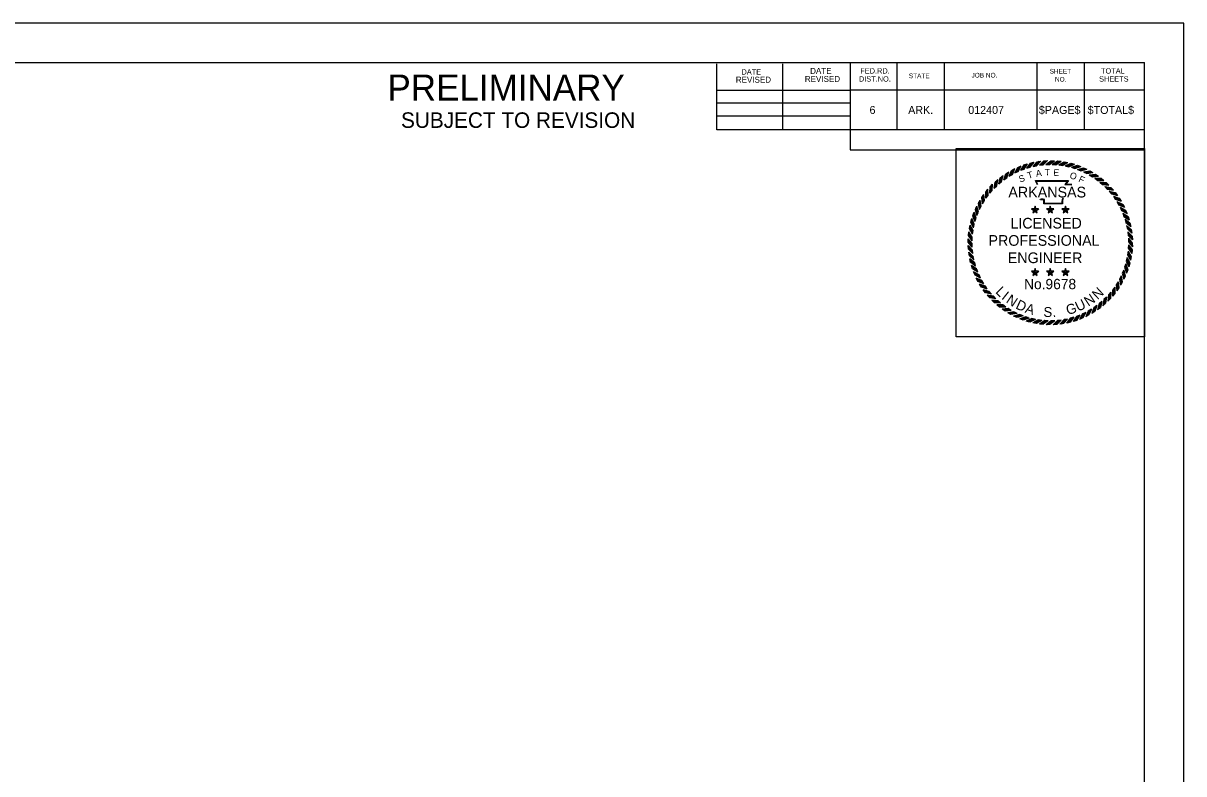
# Model space of a CAD drawing. Extents: x 0 to 1228740, y 0 to 152440.
# Drawn here: x 17 to 34, y 11 to 22 of the extents above; entities that cross this region are included whole.
import ezdxf

# ---------------------------------------------------------------- set-up
doc = ezdxf.new("R2010")
doc.units = 0
for name, color, linetype in [('R_Border', 7, 'Continuous'), ('R_Draft', 7, 'Continuous'), ('R_No Plot', 7, 'Continuous'), ('STAMP', 7, 'Continuous')]:
    doc.layers.add(name, color=color, linetype=linetype)

msp = doc.modelspace()

# ---------------------------------------------------------------- linework, layer by layer
at = {"layer": 'R_Border'}
for p, q in [((1.516, 21.423), (33.423, 21.423)), ((29.113, 21.423), (29.113, 20.143)), ((29.797, 21.423), (29.797, 20.435)), ((30.491, 21.423), (30.491, 20.435)), ((31.849, 21.423), (31.849, 20.435)), ((32.543, 21.423), (32.543, 20.435)), ((33.423, 0.577), (33.423, 21.423)), ((27.159, 20.435), (27.159, 21.403)), ((28.127, 20.435), (28.127, 21.403)), ((33.423, 21.131), (33.423, 21.131)), ((27.159, 21.021), (29.113, 21.021)), ((33.423, 21.021), (29.113, 21.021)), ((27.159, 20.835), (29.113, 20.835)), ((27.159, 20.641), (29.113, 20.641)), ((33.423, 20.435), (27.159, 20.435)), ((29.113, 20.143), (33.423, 20.143))]:
    msp.add_line(p, q, dxfattribs=at)
msp.add_lwpolyline([(34, 22), (0, 22), (0, 0), (34, 0)], close=True, dxfattribs=at)
at = {"layer": 'R_No Plot'}
msp.add_lwpolyline([(30.667, 20.162), (33.423, 20.162), (33.423, 17.405), (30.667, 17.405)], close=True, dxfattribs=at)
at = {"layer": 'STAMP'}
for p, q in [((31.568, 19.886), (31.616, 19.908)), ((31.66, 19.922), (31.71, 19.94)), ((31.701, 19.877), (31.752, 19.891)), ((31.756, 19.95), (31.807, 19.963)), ((31.792, 19.902), (31.844, 19.911)), ((31.853, 19.97), (31.905, 19.979)), ((31.885, 19.919), (31.938, 19.924)), ((31.952, 19.982), (32.004, 19.986)), ((31.98, 19.928), (32.032, 19.928)), ((32.051, 19.985), (32.104, 19.985)), ((32.074, 19.93), (32.127, 19.926)), ((32.15, 19.981), (32.203, 19.977)), ((32.169, 19.924), (32.221, 19.915)), ((32.249, 19.968), (32.301, 19.96)), ((32.263, 19.909), (32.314, 19.897)), ((32.346, 19.947), (32.397, 19.934)), ((32.441, 19.918), (32.491, 19.901)), ((31.312, 19.736), (31.353, 19.768)), ((31.364, 19.706), (31.408, 19.736)), ((31.393, 19.793), (31.437, 19.822)), ((31.443, 19.759), (31.489, 19.785)), ((31.478, 19.843), (31.524, 19.869)), ((31.525, 19.806), (31.573, 19.827)), ((31.611, 19.845), (31.661, 19.863)), ((32.355, 19.888), (32.405, 19.871)), ((32.445, 19.858), (32.494, 19.837)), ((32.532, 19.822), (32.579, 19.797)), ((32.533, 19.881), (32.582, 19.861)), ((32.616, 19.778), (32.661, 19.749)), ((32.622, 19.837), (32.669, 19.813)), ((32.697, 19.727), (32.739, 19.695)), ((32.707, 19.786), (32.752, 19.758)), ((32.788, 19.728), (32.83, 19.696)), ((31.1, 19.526), (31.132, 19.568)), ((31.158, 19.511), (31.194, 19.55)), ((31.165, 19.602), (31.2, 19.641)), ((31.221, 19.582), (31.26, 19.618)), ((31.235, 19.672), (31.274, 19.708)), ((31.29, 19.647), (31.331, 19.68)), ((32.772, 19.67), (32.811, 19.635)), ((32.843, 19.607), (32.879, 19.568)), ((32.863, 19.663), (32.902, 19.628)), ((32.933, 19.593), (32.969, 19.554)), ((30.991, 19.361), (31.016, 19.407)), ((31.042, 19.446), (31.071, 19.49)), ((31.051, 19.355), (31.079, 19.4)), ((31.101, 19.435), (31.133, 19.477)), ((32.908, 19.538), (32.941, 19.497)), ((32.968, 19.464), (32.997, 19.42)), ((32.997, 19.517), (33.03, 19.475)), ((33.021, 19.386), (33.046, 19.34)), ((33.054, 19.436), (33.083, 19.392)), ((30.91, 19.179), (30.927, 19.229)), ((30.947, 19.272), (30.968, 19.32)), ((30.97, 19.184), (30.991, 19.232)), ((31.007, 19.271), (31.032, 19.318)), ((31.874, 19.281), (31.768, 19.281)), ((31.768, 19.281), (31.854, 19.219)), ((31.821, 19.32), (31.788, 19.219)), ((31.788, 19.219), (31.875, 19.281)), ((31.814, 19.264), (31.829, 19.264)), ((31.854, 19.219), (31.821, 19.32)), ((31.821, 19.27), (31.821, 19.256)), ((32.098, 19.281), (31.991, 19.281)), ((31.992, 19.281), (32.078, 19.219)), ((32.045, 19.32), (32.012, 19.219)), ((32.012, 19.219), (32.098, 19.281)), ((32.037, 19.264), (32.053, 19.264)), ((32.078, 19.219), (32.045, 19.32)), ((32.045, 19.27), (32.045, 19.256)), ((32.321, 19.281), (32.215, 19.281)), ((32.215, 19.281), (32.301, 19.219)), ((32.268, 19.32), (32.235, 19.219)), ((32.235, 19.219), (32.321, 19.281)), ((32.261, 19.264), (32.276, 19.264)), ((32.301, 19.219), (32.268, 19.32)), ((32.268, 19.27), (32.268, 19.256)), ((33.067, 19.303), (33.089, 19.255)), ((33.105, 19.35), (33.13, 19.304)), ((33.107, 19.217), (33.124, 19.167)), ((33.148, 19.261), (33.169, 19.213)), ((30.881, 19.084), (30.894, 19.136)), ((30.919, 19.001), (30.931, 19.053)), ((30.941, 19.094), (30.957, 19.144)), ((33.139, 19.128), (33.152, 19.077)), ((33.183, 19.168), (33.201, 19.118)), ((33.211, 19.073), (33.225, 19.022)), ((30.848, 18.889), (30.852, 18.941)), ((30.861, 18.987), (30.869, 19.039)), ((30.905, 18.908), (30.913, 18.96)), ((33.163, 19.036), (33.173, 18.984)), ((33.18, 18.943), (33.185, 18.891)), ((33.231, 18.975), (33.24, 18.923)), ((33.243, 18.877), (33.248, 18.824)), ((30.847, 18.69), (30.842, 18.743)), ((30.843, 18.79), (30.843, 18.842)), ((30.898, 18.813), (30.902, 18.866)), ((30.9, 18.718), (30.899, 18.771)), ((33.191, 18.754), (33.187, 18.701)), ((33.19, 18.849), (33.19, 18.796)), ((33.246, 18.777), (33.247, 18.725)), ((30.859, 18.592), (30.849, 18.644)), ((30.878, 18.494), (30.865, 18.545)), ((30.909, 18.624), (30.904, 18.677)), ((30.926, 18.531), (30.917, 18.583)), ((33.171, 18.566), (33.158, 18.514)), ((33.185, 18.659), (33.177, 18.607)), ((33.229, 18.58), (33.221, 18.528)), ((33.242, 18.678), (33.238, 18.626)), ((30.906, 18.399), (30.889, 18.449)), ((30.951, 18.439), (30.938, 18.49)), ((30.983, 18.35), (30.966, 18.4)), ((31.874, 18.365), (31.768, 18.365)), ((31.768, 18.365), (31.854, 18.302)), ((31.821, 18.403), (31.788, 18.302)), ((31.788, 18.302), (31.875, 18.365)), ((31.854, 18.302), (31.821, 18.404)), ((32.098, 18.365), (31.991, 18.365)), ((31.992, 18.365), (32.078, 18.302)), ((32.045, 18.403), (32.012, 18.302)), ((32.012, 18.302), (32.098, 18.365)), ((32.078, 18.302), (32.045, 18.404)), ((32.321, 18.365), (32.215, 18.365)), ((32.215, 18.365), (32.301, 18.302)), ((32.268, 18.403), (32.235, 18.302)), ((32.235, 18.302), (32.321, 18.365)), ((32.301, 18.302), (32.268, 18.404)), ((33.12, 18.383), (33.099, 18.335)), ((33.149, 18.473), (33.132, 18.423)), ((33.179, 18.388), (33.163, 18.338)), ((33.208, 18.483), (33.196, 18.431)), ((30.942, 18.306), (30.92, 18.354)), ((30.985, 18.217), (30.96, 18.263)), ((31.023, 18.264), (31.001, 18.312)), ((31.069, 18.181), (31.043, 18.227)), ((31.814, 18.348), (31.829, 18.348)), ((31.821, 18.353), (31.821, 18.34)), ((32.037, 18.348), (32.053, 18.348)), ((32.045, 18.353), (32.045, 18.34)), ((32.261, 18.348), (32.276, 18.348)), ((32.268, 18.353), (32.268, 18.34)), ((33.039, 18.212), (33.011, 18.167)), ((33.083, 18.296), (33.058, 18.249)), ((33.099, 18.206), (33.074, 18.16)), ((33.143, 18.295), (33.122, 18.247)), ((31.035, 18.131), (31.006, 18.175)), ((31.093, 18.05), (31.06, 18.092)), ((31.122, 18.103), (31.093, 18.147)), ((31.181, 18.029), (31.149, 18.07)), ((32.931, 18.056), (32.896, 18.017)), ((32.988, 18.132), (32.956, 18.09)), ((32.989, 18.041), (32.957, 17.999)), ((33.047, 18.121), (33.019, 18.077)), ((31.157, 17.974), (31.121, 18.013)), ((31.226, 17.904), (31.187, 17.939)), ((31.247, 17.96), (31.211, 17.999)), ((31.302, 17.839), (31.26, 17.871)), ((31.317, 17.897), (31.278, 17.932)), ((31.393, 17.84), (31.351, 17.872)), ((32.726, 17.861), (32.682, 17.831)), ((32.8, 17.92), (32.758, 17.887)), ((32.854, 17.895), (32.816, 17.859)), ((32.868, 17.985), (32.83, 17.949)), ((32.925, 17.965), (32.889, 17.926)), ((31.382, 17.781), (31.338, 17.809)), ((31.468, 17.73), (31.421, 17.754)), ((31.473, 17.789), (31.429, 17.818)), ((31.557, 17.686), (31.508, 17.706)), ((31.557, 17.746), (31.511, 17.77)), ((31.645, 17.709), (31.596, 17.73)), ((31.735, 17.679), (31.685, 17.696)), ((32.389, 17.69), (32.338, 17.676)), ((32.478, 17.722), (32.429, 17.704)), ((32.522, 17.681), (32.474, 17.659)), ((32.564, 17.761), (32.516, 17.74)), ((32.611, 17.724), (32.565, 17.698)), ((32.647, 17.808), (32.601, 17.782)), ((32.697, 17.774), (32.653, 17.745)), ((32.778, 17.831), (32.737, 17.799)), ((31.649, 17.649), (31.599, 17.666)), ((31.744, 17.62), (31.693, 17.633)), ((31.827, 17.658), (31.776, 17.67)), ((31.841, 17.599), (31.789, 17.607)), ((31.921, 17.643), (31.869, 17.652)), ((31.939, 17.586), (31.887, 17.59)), ((32.015, 17.637), (31.963, 17.641)), ((32.039, 17.582), (31.986, 17.581)), ((32.11, 17.639), (32.057, 17.638)), ((32.138, 17.585), (32.085, 17.581)), ((32.204, 17.648), (32.152, 17.643)), ((32.237, 17.597), (32.185, 17.588)), ((32.298, 17.665), (32.246, 17.656)), ((32.334, 17.617), (32.283, 17.604)), ((32.429, 17.645), (32.38, 17.627))]:
    msp.add_line(p, q, dxfattribs=at)
for points in [[(31.541, 19.813), (31.583, 19.893)], [(31.557, 19.82), (31.6, 19.901)], [(31.573, 19.827), (31.616, 19.908)], [(31.611, 19.845), (31.66, 19.922)], [(31.627, 19.851), (31.676, 19.927)], [(31.644, 19.857), (31.694, 19.934)], [(31.661, 19.863), (31.71, 19.94)], [(31.7, 19.877), (31.756, 19.95)], [(31.717, 19.881), (31.772, 19.954)], [(31.735, 19.887), (31.79, 19.959)], [(31.752, 19.891), (31.807, 19.963)], [(31.792, 19.902), (31.853, 19.97)], [(31.809, 19.905), (31.87, 19.973)], [(31.827, 19.908), (31.888, 19.976)], [(31.844, 19.911), (31.905, 19.979)], [(31.885, 19.919), (31.952, 19.982)], [(31.902, 19.92), (31.969, 19.983)], [(31.92, 19.923), (31.987, 19.985)], [(31.938, 19.924), (32.004, 19.986)], [(31.98, 19.928), (32.051, 19.984)], [(31.996, 19.928), (32.068, 19.984)], [(32.015, 19.929), (32.087, 19.985)], [(32.032, 19.928), (32.104, 19.985)], [(32.074, 19.93), (32.15, 19.981)], [(32.091, 19.928), (32.167, 19.979)], [(32.109, 19.928), (32.185, 19.978)], [(32.127, 19.926), (32.203, 19.977)], [(32.169, 19.924), (32.249, 19.968)], [(32.186, 19.921), (32.265, 19.965)], [(32.204, 19.918), (32.283, 19.962)], [(32.221, 19.915), (32.301, 19.96)], [(32.263, 19.909), (32.346, 19.947)], [(32.279, 19.905), (32.362, 19.943)], [(32.297, 19.901), (32.38, 19.939)], [(32.314, 19.897), (32.397, 19.934)], [(32.355, 19.888), (32.441, 19.918)], [(32.371, 19.882), (32.457, 19.913)], [(32.388, 19.877), (32.474, 19.907)], [(32.405, 19.871), (32.491, 19.901)], [(31.29, 19.647), (31.312, 19.735)], [(31.303, 19.657), (31.325, 19.746)], [(31.318, 19.669), (31.339, 19.758)], [(31.331, 19.68), (31.353, 19.768)], [(31.364, 19.706), (31.393, 19.793)], [(31.378, 19.716), (31.407, 19.802)], [(31.393, 19.726), (31.422, 19.813)], [(31.408, 19.736), (31.437, 19.822)], [(31.442, 19.759), (31.478, 19.843)], [(31.457, 19.767), (31.493, 19.851)], [(31.473, 19.777), (31.509, 19.86)], [(31.489, 19.785), (31.524, 19.869)], [(31.525, 19.806), (31.568, 19.886)], [(32.445, 19.858), (32.533, 19.881)], [(32.46, 19.851), (32.549, 19.875)], [(32.477, 19.845), (32.566, 19.868)], [(32.493, 19.838), (32.582, 19.861)], [(32.532, 19.821), (32.622, 19.837)], [(32.547, 19.813), (32.637, 19.829)], [(32.564, 19.805), (32.653, 19.821)], [(32.579, 19.797), (32.669, 19.813)], [(32.616, 19.778), (32.707, 19.786)], [(32.631, 19.768), (32.721, 19.777)], [(32.646, 19.759), (32.737, 19.767)], [(32.661, 19.749), (32.752, 19.758)], [(32.696, 19.727), (32.788, 19.728)], [(31.122, 19.463), (31.122, 19.555)], [(31.133, 19.477), (31.132, 19.568)], [(31.158, 19.511), (31.165, 19.602)], [(31.17, 19.523), (31.176, 19.614)], [(31.182, 19.537), (31.188, 19.628)], [(31.194, 19.55), (31.2, 19.641)], [(31.221, 19.582), (31.235, 19.672)], [(31.234, 19.593), (31.248, 19.683)], [(31.247, 19.606), (31.261, 19.696)], [(31.26, 19.618), (31.274, 19.708)], [(31.855, 19.632), (31.827, 19.693), (32.313, 19.693), (32.272, 19.642), (32.305, 19.642), (32.333, 19.643), (32.361, 19.64)], [(31.862, 19.635), (31.839, 19.685), (32.297, 19.685), (32.256, 19.634), (32.306, 19.635), (32.333, 19.635), (32.36, 19.632)], [(32.71, 19.717), (32.801, 19.718)], [(32.725, 19.706), (32.816, 19.707)], [(32.739, 19.695), (32.83, 19.696)], [(32.772, 19.67), (32.863, 19.663)], [(32.785, 19.659), (32.876, 19.652)], [(32.799, 19.647), (32.889, 19.64)], [(32.811, 19.635), (32.902, 19.628)], [(32.843, 19.607), (32.933, 19.593)], [(32.854, 19.595), (32.944, 19.58)], [(32.867, 19.581), (32.957, 19.567)], [(32.879, 19.569), (32.969, 19.554)], [(31.023, 19.302), (31.007, 19.392)], [(31.031, 19.318), (31.016, 19.407)], [(31.051, 19.355), (31.042, 19.446)], [(31.06, 19.369), (31.051, 19.46)], [(31.069, 19.385), (31.061, 19.476)], [(31.079, 19.4), (31.071, 19.49)], [(31.101, 19.435), (31.1, 19.526)], [(31.112, 19.449), (31.111, 19.54)], [(32.236, 19.428), (32.228, 19.422), (32.225, 19.411), (32.223, 19.386), (32.223, 19.353), (31.951, 19.353), (31.951, 19.398), (31.951, 19.408), (31.94, 19.411), (31.902, 19.411), (31.895, 19.422)], [(32.232, 19.434), (32.221, 19.426), (32.218, 19.413), (32.215, 19.387), (32.215, 19.36), (31.959, 19.36), (31.959, 19.398), (31.959, 19.414), (31.942, 19.419), (31.906, 19.419), (31.901, 19.426)], [(32.908, 19.538), (32.997, 19.517)], [(32.919, 19.525), (33.007, 19.503)], [(32.93, 19.511), (33.019, 19.489)], [(32.941, 19.497), (33.03, 19.475)], [(32.968, 19.464), (33.054, 19.436)], [(32.977, 19.45), (33.063, 19.421)], [(32.987, 19.435), (33.074, 19.406)], [(32.997, 19.42), (33.083, 19.392)], [(33.021, 19.386), (33.104, 19.35)], [(30.952, 19.127), (30.921, 19.213)], [(30.957, 19.144), (30.927, 19.23)], [(30.97, 19.184), (30.947, 19.272)], [(30.977, 19.199), (30.954, 19.287)], [(30.984, 19.216), (30.961, 19.304)], [(30.991, 19.232), (30.968, 19.32)], [(31.007, 19.271), (30.991, 19.361)], [(31.015, 19.286), (30.999, 19.376)], [(33.029, 19.371), (33.113, 19.335)], [(33.038, 19.355), (33.122, 19.319)], [(33.046, 19.34), (33.13, 19.304)], [(33.067, 19.303), (33.148, 19.261)], [(33.074, 19.288), (33.154, 19.245)], [(33.082, 19.271), (33.162, 19.229)], [(33.089, 19.255), (33.169, 19.213)], [(33.106, 19.217), (33.183, 19.168)], [(30.919, 19.001), (30.881, 19.084)], [(30.923, 19.018), (30.886, 19.101)], [(30.927, 19.036), (30.89, 19.119)], [(30.931, 19.053), (30.894, 19.136)], [(30.941, 19.093), (30.91, 19.179)], [(30.946, 19.11), (30.916, 19.195)], [(33.112, 19.201), (33.189, 19.152)], [(33.118, 19.184), (33.195, 19.135)], [(33.124, 19.167), (33.201, 19.118)], [(33.139, 19.128), (33.211, 19.073)], [(33.143, 19.111), (33.215, 19.056)], [(33.148, 19.094), (33.22, 19.039)], [(33.152, 19.077), (33.225, 19.022)], [(30.898, 18.813), (30.848, 18.889)], [(30.9, 18.83), (30.849, 18.906)], [(30.901, 18.848), (30.85, 18.924)], [(30.902, 18.866), (30.852, 18.941)], [(30.905, 18.908), (30.861, 18.987)], [(30.908, 18.924), (30.863, 19.004)], [(30.91, 18.942), (30.866, 19.022)], [(30.913, 18.96), (30.869, 19.039)], [(33.163, 19.036), (33.231, 18.975)], [(33.166, 19.02), (33.234, 18.959)], [(33.17, 19.002), (33.237, 18.941)], [(33.173, 18.984), (33.24, 18.923)], [(33.18, 18.943), (33.243, 18.877)], [(33.182, 18.926), (33.244, 18.86)], [(33.184, 18.908), (33.246, 18.842)], [(33.185, 18.891), (33.248, 18.824)], [(30.904, 18.676), (30.842, 18.743)], [(30.899, 18.771), (30.843, 18.842)], [(30.899, 18.753), (30.843, 18.825)], [(30.9, 18.735), (30.843, 18.807)], [(30.9, 18.718), (30.843, 18.79)], [(30.906, 18.659), (30.843, 18.725)], [(30.908, 18.641), (30.845, 18.707)], [(33.187, 18.701), (33.238, 18.626)], [(33.189, 18.719), (33.239, 18.643)], [(33.19, 18.849), (33.246, 18.777)], [(33.19, 18.832), (33.246, 18.761)], [(33.19, 18.814), (33.247, 18.742)], [(33.19, 18.796), (33.247, 18.725)], [(33.19, 18.737), (33.24, 18.661)], [(33.191, 18.754), (33.242, 18.678)], [(30.909, 18.624), (30.847, 18.69)], [(30.917, 18.583), (30.849, 18.644)], [(30.92, 18.565), (30.852, 18.626)], [(30.924, 18.547), (30.856, 18.608)], [(30.926, 18.531), (30.859, 18.592)], [(30.938, 18.49), (30.865, 18.545)], [(33.163, 18.531), (33.2, 18.448)], [(33.167, 18.549), (33.204, 18.466)], [(33.171, 18.566), (33.208, 18.483)], [(33.177, 18.607), (33.221, 18.528)], [(33.18, 18.625), (33.224, 18.545)], [(33.182, 18.643), (33.226, 18.563)], [(33.185, 18.66), (33.229, 18.58)], [(30.942, 18.473), (30.869, 18.528)], [(30.947, 18.456), (30.874, 18.511)], [(30.951, 18.439), (30.879, 18.494)], [(30.966, 18.4), (30.889, 18.449)], [(30.971, 18.383), (30.894, 18.432)], [(30.978, 18.366), (30.901, 18.415)], [(30.983, 18.35), (30.906, 18.399)], [(33.113, 18.368), (33.136, 18.28)], [(33.12, 18.383), (33.143, 18.295)], [(33.132, 18.423), (33.163, 18.338)], [(33.138, 18.44), (33.168, 18.354)], [(33.143, 18.458), (33.174, 18.372)], [(33.149, 18.474), (33.179, 18.388)], [(33.158, 18.514), (33.196, 18.431)], [(31.001, 18.312), (30.92, 18.355)], [(31.008, 18.296), (30.927, 18.338)], [(31.016, 18.279), (30.935, 18.322)], [(31.023, 18.264), (30.942, 18.306)], [(31.043, 18.227), (30.96, 18.263)], [(31.052, 18.212), (30.968, 18.248)], [(31.061, 18.196), (30.977, 18.232)], [(31.069, 18.181), (30.985, 18.217)], [(33.03, 18.198), (33.038, 18.107)], [(33.039, 18.212), (33.047, 18.121)], [(33.058, 18.249), (33.074, 18.16)], [(33.067, 18.265), (33.082, 18.175)], [(33.075, 18.281), (33.091, 18.191)], [(33.083, 18.296), (33.099, 18.206)], [(33.099, 18.335), (33.122, 18.247)], [(33.106, 18.351), (33.129, 18.263)], [(31.093, 18.147), (31.006, 18.175)], [(31.102, 18.132), (31.016, 18.161)], [(31.113, 18.117), (31.026, 18.146)], [(31.122, 18.103), (31.036, 18.131)], [(31.149, 18.07), (31.06, 18.092)], [(31.159, 18.056), (31.071, 18.078)], [(31.171, 18.042), (31.082, 18.064)], [(31.181, 18.029), (31.093, 18.05)], [(32.908, 18.03), (32.901, 17.939)], [(32.92, 18.044), (32.913, 17.953)], [(32.931, 18.056), (32.925, 17.965)], [(32.956, 18.09), (32.957, 17.999)], [(32.967, 18.104), (32.968, 18.013)], [(32.978, 18.118), (32.979, 18.027)], [(32.988, 18.132), (32.989, 18.041)], [(33.011, 18.167), (33.019, 18.077)], [(33.02, 18.182), (33.029, 18.091)], [(31.211, 17.999), (31.12, 18.013)], [(31.222, 17.986), (31.132, 18)], [(31.235, 17.973), (31.145, 17.987)], [(31.247, 17.96), (31.157, 17.974)], [(31.278, 17.932), (31.187, 17.939)], [(31.291, 17.92), (31.2, 17.927)], [(31.305, 17.908), (31.214, 17.915)], [(31.317, 17.897), (31.227, 17.904)], [(31.351, 17.872), (31.26, 17.871)], [(31.365, 17.861), (31.274, 17.86)], [(31.38, 17.85), (31.289, 17.849)], [(32.711, 17.852), (32.683, 17.765)], [(32.726, 17.861), (32.697, 17.774)], [(32.758, 17.887), (32.737, 17.799)], [(32.772, 17.898), (32.751, 17.809)], [(32.786, 17.91), (32.765, 17.821)], [(32.8, 17.92), (32.778, 17.832)], [(32.83, 17.949), (32.816, 17.859)], [(32.843, 17.961), (32.829, 17.871)], [(32.856, 17.974), (32.842, 17.884)], [(32.868, 17.985), (32.854, 17.895)], [(32.896, 18.017), (32.889, 17.926)], [(31.393, 17.84), (31.302, 17.839)], [(31.429, 17.818), (31.338, 17.809)], [(31.443, 17.808), (31.353, 17.8)], [(31.459, 17.799), (31.368, 17.79)], [(31.473, 17.789), (31.383, 17.781)], [(31.511, 17.77), (31.421, 17.754)], [(31.526, 17.762), (31.436, 17.746)], [(31.542, 17.754), (31.453, 17.738)], [(31.557, 17.746), (31.468, 17.73)], [(31.596, 17.73), (31.508, 17.706)], [(31.612, 17.722), (31.524, 17.699)], [(31.629, 17.716), (31.541, 17.692)], [(31.645, 17.709), (31.557, 17.686)], [(31.685, 17.696), (31.599, 17.666)], [(31.701, 17.69), (31.615, 17.66)], [(31.719, 17.685), (31.633, 17.655)], [(32.355, 17.681), (32.3, 17.608)], [(32.373, 17.686), (32.317, 17.613)], [(32.389, 17.69), (32.334, 17.617)], [(32.429, 17.704), (32.379, 17.627)], [(32.445, 17.71), (32.396, 17.633)], [(32.462, 17.716), (32.413, 17.64)], [(32.478, 17.722), (32.429, 17.645)], [(32.516, 17.74), (32.474, 17.659)], [(32.532, 17.747), (32.49, 17.666)], [(32.549, 17.755), (32.506, 17.674)], [(32.565, 17.761), (32.522, 17.681)], [(32.601, 17.782), (32.565, 17.698)], [(32.616, 17.79), (32.581, 17.707)], [(32.632, 17.8), (32.596, 17.716)], [(32.647, 17.808), (32.611, 17.724)], [(32.682, 17.831), (32.653, 17.745)], [(32.696, 17.841), (32.668, 17.755)], [(31.735, 17.679), (31.649, 17.649)], [(31.776, 17.67), (31.693, 17.633)], [(31.793, 17.666), (31.71, 17.628)], [(31.811, 17.662), (31.728, 17.624)], [(31.827, 17.658), (31.744, 17.62)], [(31.869, 17.652), (31.789, 17.607)], [(31.886, 17.649), (31.806, 17.605)], [(31.904, 17.646), (31.824, 17.602)], [(31.921, 17.644), (31.841, 17.599)], [(31.963, 17.641), (31.887, 17.59)], [(31.98, 17.64), (31.904, 17.589)], [(31.998, 17.639), (31.923, 17.588)], [(32.015, 17.637), (31.94, 17.587)], [(32.057, 17.638), (31.986, 17.581)], [(32.075, 17.638), (32.004, 17.581)], [(32.093, 17.639), (32.022, 17.582)], [(32.11, 17.639), (32.039, 17.582)], [(32.152, 17.643), (32.085, 17.581)], [(32.169, 17.644), (32.103, 17.582)], [(32.188, 17.647), (32.121, 17.584)], [(32.204, 17.648), (32.138, 17.586)], [(32.246, 17.656), (32.185, 17.588)], [(32.263, 17.659), (32.202, 17.591)], [(32.281, 17.662), (32.22, 17.595)], [(32.298, 17.665), (32.237, 17.597)], [(32.338, 17.676), (32.283, 17.604)]]:
    msp.add_lwpolyline(points, dxfattribs=at)

# ---------------------------------------------------------------- texts
at = {"layer": 'R_Border'}
for s, height, p in [('DATE', 0.0782, (27.521, 21.247)), ('DATE', 0.0879, (28.527, 21.257)), ('FED.RD.', 0.0782, (29.261, 21.262)), ('STATE', 0.0684, (29.973, 21.194)), ('JOB NO.', 0.0684, (30.891, 21.204)), ('SHEET', 0.0684, (32.035, 21.262)), ('TOTAL', 0.0782, (32.787, 21.262)), ('REVISED', 0.0879, (27.438, 21.128)), ('REVISED', 0.0879, (28.449, 21.139)), ('DIST.NO.', 0.0782, (29.241, 21.144)), ('NO.', 0.0684, (32.113, 21.144)), ('SHEETS', 0.0782, (32.759, 21.144)), ('6', 0.117, (29.397, 20.67)), ('ARK.', 0.1172, (29.963, 20.67)), ('012407', 0.1172, (30.843, 20.67)), ('$PAGE$', 0.1172, (31.877, 20.67)), ('$TOTAL$', 0.1172, (32.592, 20.67))]:
    msp.add_text(s, height=height, dxfattribs=at).set_placement(p)
at = {"layer": 'R_Draft'}
for s, height, p in [('PRELIMINARY', 0.38359, (22.335, 20.864)), ('SUBJECT TO REVISION', 0.22743, (22.534, 20.466))]:
    msp.add_text(s, height=height, rotation=0, dxfattribs=at).set_placement(p)
at = {"layer": 'STAMP'}
for s, height, rotation, p in [('S', 0.0959, 19.7726, (31.602, 19.664)), ('T', 0.0959, 16.9015, (31.724, 19.718)), ('A', 0.0959, 8.6788, (31.84, 19.749)), ('T', 0.0959, 1.4789, (31.964, 19.768)), ('E', 0.0959, 356.672, (32.087, 19.765)), ('O', 0.0959, 341.2218, (32.32, 19.732)), ('F', 0.0959, 335.3628, (32.449, 19.682)), ('L', 0.146, 315.1295, (31.233, 18.055)), ('I', 0.146, 321.696, (31.321, 17.967)), ('N', 0.146, 326.0736, (31.386, 17.914)), ('N', 0.146, 33.9264, (32.601, 17.845)), ('N', 0.146, 42.6817, (32.738, 17.94)), ('D', 0.146, 334.8288, (31.526, 17.824)), ('A', 0.146, 342.8544, (31.665, 17.761)), ('G', 0.146, 16.7808, (32.3, 17.722)), ('U', 0.146, 25.1712, (32.452, 17.771)), ('S', 0.146, 357.8112, (31.941, 17.697)), ('.', 0.146, 5.1072, (32.08, 17.693))]:
    msp.add_text(s, height=height, rotation=rotation, dxfattribs=at).set_placement(p)
for s, height, p in [('ARKANSAS', 0.1564, (31.43, 19.446)), ('LICENSED', 0.1564, (31.46, 18.991)), ('PROFESSIONAL', 0.15644, (31.139, 18.738)), ('ENGINEER', 0.1564, (31.422, 18.484)), ('No.9678', 0.1509, (31.66, 18.102))]:
    msp.add_text(s, height=height, dxfattribs=at).set_placement(p)

doc.saveas('drawing.dxf')
